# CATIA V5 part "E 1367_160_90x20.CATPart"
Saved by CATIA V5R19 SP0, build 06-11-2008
Definition: E 1367_160_90x20
Nomenclature: E 1367_160_90x20
Description: PART-E 1367_160_90x20-DESC
Material "Steel": density 7860 kg/m3, Young's modulus 2e+11 Pa, Poisson ratio 0.266, thermal expansion 1.17e-05 1/K
Bounding box of the stored display mesh (mm): x -80 to 80, y -80 to 80, z -12 to 8
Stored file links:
  G:\UTB\Kombinované\Bakalářská práce\Catia\FORMA\E 1367_160_90x20.CATPart
  D:\Aplikace\CATIA\Nová složka\win_b64\startup\materials\Catalog.CATMaterial
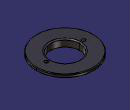
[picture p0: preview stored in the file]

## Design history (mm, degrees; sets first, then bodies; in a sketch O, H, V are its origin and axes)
Body1 "E 1367_160_90x20" (main body)
  Solid1: solid without history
